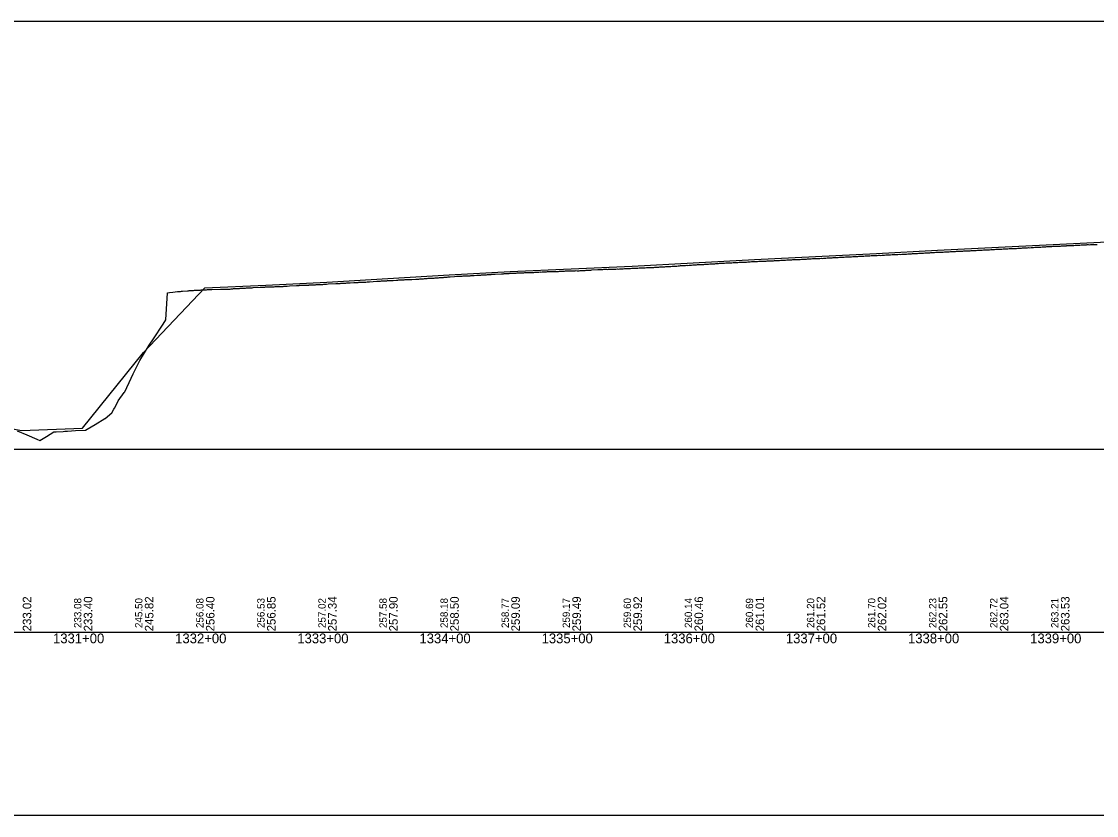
# Model space of a CAD drawing. Extents: x 2898 to 49495, y -15038 to -13538.
# Drawn here: x 22503 to 23383, y -15038 to -14388 of the extents above; entities that cross this region are included whole.
import ezdxf

# ---------------------------------------------------------------- set-up
doc = ezdxf.new("R2010")
doc.units = 0
for name, color, linetype in [('RD_DDB_Profile_EX', 7, 'Continuous'), ('RD_DDB_Profile_PR', 7, 'Continuous'), ('RD_DDB_StaTX', 7, 'Continuous'), ('RD_DDB_StripGrade', 7, 'Continuous'), ('RD_GPK_Profile_Cell', 7, 'Continuous'), ('RD_SHT_ShtClip', 7, 'Continuous')]:
    doc.layers.add(name, color=color, linetype=linetype)

msp = doc.modelspace()

# ---------------------------------------------------------------- linework, layer by layer
at = {"layer": 'RD_DDB_Profile_EX'}
for points in [[(23256.97, -14577.17), (23257.97, -14577.18), (23258.97, -14577.07), (23259.97, -14577.04), (23260.97, -14576.99), (23261.96, -14577.01), (23262.97, -14576.98), (23263.97, -14576.82), (23264.96, -14576.73), (23265.97, -14576.71), (23266.96, -14576.8), (23267.96, -14576.66), (23268.96, -14576.57), (23269.96, -14576.52), (23270.97, -14576.51), (23271.96, -14576.5), (23272.97, -14576.4), (23273.96, -14576.41), (23274.97, -14576.33), (23275.97, -14576.28), (23276.97, -14576.2), (23277.97, -14576.15), (23278.96, -14576.15), (23279.96, -14576.07), (23280.97, -14576.05), (23281.96, -14576.05), (23282.96, -14575.96), (23283.96, -14575.92), (23284.96, -14575.82), (23285.97, -14575.78), (23286.96, -14575.76), (23287.96, -14575.63), (23288.97, -14575.63), (23289.96, -14575.6), (23290.97, -14575.5), (23291.96, -14575.49), (23292.96, -14575.44), (23293.97, -14575.37), (23294.96, -14575.36), (23295.96, -14575.29), (23296.97, -14575.15), (23297.96, -14575.13), (23298.96, -14575.08), (23299.96, -14574.99), (23300.96, -14574.94), (23301.96, -14574.86), (23302.96, -14574.89), (23303.96, -14574.8), (23304.97, -14574.71), (23305.96, -14574.73), (23306.96, -14574.67), (23307.96, -14574.59), (23308.96, -14574.6), (23309.96, -14574.54), (23310.96, -14574.44), (23311.96, -14574.4), (23312.96, -14574.36), (23313.96, -14574.35), (23314.96, -14574.33), (23315.96, -14574.24), (23316.96, -14574.2), (23317.96, -14574.16), (23318.96, -14574.12), (23319.96, -14574.06), (23320.96, -14574.01), (23321.96, -14573.93), (23322.96, -14573.87), (23323.96, -14573.82), (23324.96, -14573.78), (23325.96, -14573.73), (23326.96, -14573.7), (23327.96, -14573.59), (23328.95, -14573.63), (23329.96, -14573.54), (23330.96, -14573.48), (23331.96, -14573.44), (23332.96, -14573.34), (23333.96, -14573.29), (23334.96, -14573.19), (23335.96, -14573.13), (23336.96, -14573.13), (23337.96, -14573.08), (23338.96, -14573.04), (23339.96, -14572.99), (23340.96, -14572.93), (23341.96, -14572.83), (23342.96, -14572.77), (23343.96, -14572.75), (23344.96, -14572.78), (23345.96, -14572.66), (23346.96, -14572.59), (23347.96, -14572.52), (23348.96, -14572.46), (23349.96, -14572.46), (23350.96, -14572.41), (23351.38, -14572.39), (23351.95, -14572.37), (23352.95, -14572.43), (23353.96, -14572.41), (23354.96, -14572.22), (23355.96, -14572.12)], [(23355.96, -14572.12), (23356.96, -14572.12), (23357.96, -14572.02), (23358.96, -14571.98), (23359.34, -14571.96), (23359.96, -14571.96), (23360.96, -14571.92), (23361.96, -14571.87), (23362.96, -14571.8), (23363.96, -14571.8), (23364.96, -14571.75), (23365.96, -14571.63), (23366.96, -14571.61), (23367.3, -14571.61), (23367.96, -14571.6), (23368.96, -14571.51), (23369.96, -14571.46), (23370.96, -14571.4), (23371.96, -14571.36), (23372.96, -14571.31), (23373.96, -14571.27), (23375.26, -14571.19), (23375.96, -14571.12), (23376.96, -14571.08), (23377.96, -14571.16), (23378.96, -14571.12), (23379.96, -14571.11), (23380.96, -14571.02), (23381.96, -14571.01), (23383.21, -14570.94), (23383.96, -14570.95)], [(23061.95, -14587.34), (23062.95, -14587.13), (23063.95, -14587.09), (23064.96, -14587.05), (23065.96, -14586.99), (23066.95, -14586.85), (23067.95, -14586.81), (23068.96, -14586.79), (23069.96, -14586.83), (23070.95, -14586.77), (23071.95, -14586.67), (23072.95, -14586.54), (23073.95, -14586.49), (23074.95, -14586.43), (23075.96, -14586.39), (23076.96, -14586.34), (23077.95, -14586.24), (23078.95, -14586.23), (23079.95, -14586.15), (23080.95, -14586.06), (23081.95, -14586.1), (23082.95, -14586.01), (23083.95, -14586.06), (23084.95, -14586.01), (23085.95, -14585.86), (23086.95, -14585.83), (23087.95, -14585.75), (23088.95, -14585.72), (23089.95, -14585.7), (23090.95, -14585.61), (23091.95, -14585.56), (23092.95, -14585.46), (23093.95, -14585.41), (23094.95, -14585.42), (23095.95, -14585.42), (23096.94, -14585.37), (23097.94, -14585.27), (23098.95, -14585.18), (23099.94, -14585.12), (23100.95, -14585.06), (23101.94, -14585.01), (23102.94, -14585.01), (23103.94, -14585.02), (23104.94, -14584.97), (23105.94, -14584.86), (23106.93, -14584.76), (23107.94, -14584.76), (23108.94, -14584.71), (23109.94, -14584.7), (23110.94, -14584.74), (23111.93, -14584.73), (23112.93, -14584.59), (23113.94, -14584.5), (23114.93, -14584.49), (23115.94, -14584.49), (23116.94, -14584.48), (23117.94, -14584.27), (23118.94, -14584.26), (23119.94, -14584.2), (23120.94, -14584.18), (23121.94, -14584.12), (23122.94, -14584.02), (23123.94, -14584.01), (23124.94, -14583.95), (23125.94, -14583.9), (23126.94, -14583.81), (23127.94, -14583.75), (23128.95, -14583.72), (23129.94, -14583.67), (23130.94, -14583.62), (23131.95, -14583.6), (23132.94, -14583.54), (23133.95, -14583.48), (23134.95, -14583.43), (23135.95, -14583.33), (23136.95, -14583.32), (23137.95, -14583.21), (23138.95, -14583.32), (23139.95, -14583.24), (23140.95, -14583.17), (23141.95, -14583.16), (23142.95, -14582.97), (23143.95, -14582.99), (23144.95, -14582.95), (23145.95, -14582.9), (23146.95, -14582.85), (23147.96, -14582.8), (23148.95, -14582.65), (23149.95, -14582.64), (23150.95, -14582.58), (23151.95, -14582.58), (23152.44, -14582.53), (23152.96, -14582.51), (23153.95, -14582.45), (23154.95, -14582.43), (23155.96, -14582.42), (23156.96, -14582.36), (23157.96, -14582.31), (23158.95, -14582.35), (23159.96, -14582.24), (23160.4, -14582.22)], [(23160.4, -14582.22), (23160.95, -14582.19), (23161.95, -14582.15), (23162.96, -14581.98), (23163.96, -14581.96), (23164.95, -14581.97), (23165.96, -14581.96), (23166.96, -14581.82), (23167.96, -14581.8), (23168.36, -14581.78), (23168.96, -14581.77), (23169.96, -14581.72), (23170.96, -14581.58), (23171.96, -14581.59), (23172.96, -14581.5), (23173.96, -14581.5), (23174.96, -14581.46), (23175.96, -14581.32), (23176.31, -14581.32), (23176.96, -14581.31), (23177.96, -14581.2), (23178.96, -14581.15), (23179.96, -14581.16), (23180.97, -14581.2), (23181.97, -14581.04), (23182.96, -14580.99), (23183.96, -14580.87), (23184.27, -14580.87), (23184.96, -14580.86), (23185.96, -14580.82), (23186.96, -14580.74), (23187.97, -14580.72), (23188.96, -14580.66), (23189.96, -14580.58), (23190.96, -14580.55), (23192.23, -14580.55), (23192.96, -14580.49), (23193.97, -14580.42), (23194.96, -14580.34), (23195.96, -14580.29), (23196.96, -14580.24), (23197.96, -14580.19), (23198.96, -14580.16), (23200.19, -14580.1), (23200.97, -14580.09), (23201.97, -14580.03), (23202.97, -14580.03), (23203.97, -14579.91), (23204.97, -14579.85), (23205.96, -14579.83), (23206.96, -14579.91), (23208.15, -14579.75), (23208.96, -14579.72), (23209.96, -14579.62), (23210.96, -14579.56), (23211.96, -14579.51), (23212.96, -14579.47), (23213.97, -14579.47), (23214.97, -14579.43), (23216.1, -14579.34), (23216.97, -14579.28), (23217.96, -14579.25), (23218.97, -14579.23), (23219.97, -14579.13), (23220.97, -14579.09), (23221.97, -14579.04), (23222.96, -14579.11), (23224.06, -14579.04), (23224.96, -14578.93), (23225.96, -14578.89), (23226.96, -14578.93), (23227.97, -14578.92), (23228.96, -14578.72), (23229.97, -14578.69), (23230.96, -14578.63), (23232.02, -14578.58), (23232.96, -14578.49), (23233.96, -14578.43), (23234.96, -14578.38), (23235.96, -14578.35), (23236.96, -14578.26), (23237.96, -14578.23), (23238.96, -14578.21), (23239.98, -14578.2), (23240.96, -14578.08), (23241.96, -14578.02), (23242.96, -14577.92), (23243.96, -14577.88), (23244.96, -14577.86), (23245.96, -14577.78), (23246.96, -14577.71), (23247.96, -14577.7), (23248.96, -14577.67), (23249.97, -14577.58), (23250.96, -14577.52), (23251.97, -14577.39), (23252.96, -14577.35), (23253.97, -14577.3), (23254.96, -14577.24), (23255.97, -14577.18), (23256.97, -14577.17)], [(22871.38, -14596.48), (22872.17, -14596.44), (22872.96, -14596.44), (22873.92, -14596.39), (22876.12, -14596.26), (22876.92, -14596.18), (22877.72, -14596.14), (22878.51, -14596.1), (22879.31, -14596.06), (22880.11, -14595.98), (22880.9, -14595.9), (22881.88, -14595.85), (22882.49, -14595.82), (22883.28, -14595.74), (22884.07, -14595.74), (22884.87, -14595.7), (22885.66, -14595.58), (22886.45, -14595.54), (22887.25, -14595.66), (22888.03, -14595.66), (22888.83, -14595.38), (22889.84, -14595.33), (22890.43, -14595.3), (22891.22, -14595.26), (22896.25, -14594.95), (22897.05, -14595.03), (22897.86, -14594.99), (22898.66, -14594.83), (22899.46, -14594.87), (22900.26, -14594.79), (22901.07, -14594.75), (22901.87, -14594.79), (22902.67, -14594.67), (22903.48, -14594.59), (22904.28, -14594.51), (22905.09, -14594.51), (22905.89, -14594.51), (22906.7, -14594.51), (22907.51, -14594.47), (22908.32, -14594.39), (22909.13, -14594.35), (22909.93, -14594.35), (22910.73, -14594.27), (22913.13, -14594.19), (22913.95, -14594.19), (22914.76, -14594.15), (22915.56, -14594.03), (22916.37, -14593.99), (22917.18, -14593.99), (22917.98, -14593.99), (22918.79, -14593.99), (22919.6, -14593.91), (22920.4, -14593.82), (22921.2, -14593.86), (22921.67, -14593.86), (22922.01, -14593.87), (22922.82, -14593.82), (22923.61, -14593.7), (22924.42, -14593.7), (22925.23, -14593.66), (22926.04, -14593.66), (22926.83, -14593.54), (22927.64, -14593.5), (22928.46, -14593.54), (22929.63, -14593.5), (22933.26, -14593.38), (22934.08, -14593.22), (22934.89, -14593.26), (22935.69, -14593.26), (22936.5, -14593.18), (22937.58, -14593.18), (22938.12, -14593.18), (22938.93, -14593.02), (22939.74, -14593.02), (22940.55, -14593.06), (22941.36, -14593.02), (22942.17, -14593.02), (22942.98, -14593.02), (22943.79, -14592.94), (22944.6, -14592.9), (22945.54, -14592.84), (22946.23, -14592.74), (22947.05, -14592.82), (22947.87, -14592.82), (22948.67, -14592.66), (22949.48, -14592.66), (22950.3, -14592.57), (22953.5, -14592.61), (22954.23, -14592.54), (22955.04, -14592.5), (22955.85, -14592.58), (22956.66, -14592.58), (22957.46, -14592.42), (22958.27, -14592.54), (22959.08, -14592.58), (22959.89, -14592.54), (22960.7, -14592.3), (22961.51, -14592.26), (22962.31, -14592.22), (22963.13, -14592.18), (22963.93, -14592.18)], [(22963.93, -14592.18), (22964.75, -14592.18), (22965.55, -14592.14), (22966.37, -14592.09), (22967.18, -14592.05), (22967.98, -14592.01), (22968.81, -14591.97), (22969.61, -14591.93), (22970.43, -14591.89), (22975.19, -14591.51), (22976, -14591.51), (22976.8, -14591.51), (22977.61, -14591.47), (22978.42, -14591.43), (22979.22, -14591.39), (22980.03, -14591.35), (22980.84, -14591.35), (22981.65, -14591.35), (22982.46, -14591.35), (22983.27, -14591.39), (22984.07, -14591.35), (22984.98, -14591.22), (22985.33, -14591.24), (22985.96, -14591.23), (22986.96, -14591.18), (22987.95, -14591.23), (22988.96, -14591.1), (22989.96, -14591.08), (22990.96, -14590.99), (22991.96, -14591.08), (22992.96, -14591.02), (22993.29, -14590.97), (22993.96, -14590.88), (22994.96, -14590.96), (22995.96, -14590.86), (22996.95, -14590.69), (22997.96, -14590.69), (22998.96, -14590.6), (22999.96, -14590.6), (23001.25, -14590.6), (23001.96, -14590.59), (23002.96, -14590.52), (23003.95, -14590.44), (23004.96, -14590.49), (23005.95, -14590.45), (23006.96, -14590.29), (23007.96, -14590.29), (23009.2, -14590.23), (23009.96, -14590.22), (23010.96, -14590.13), (23011.96, -14590.2), (23012.95, -14590.24), (23013.96, -14590.08), (23014.96, -14589.98), (23015.96, -14589.95), (23017.16, -14589.89), (23017.96, -14589.84), (23018.96, -14589.78), (23019.96, -14589.72), (23020.96, -14589.72), (23021.95, -14589.67), (23022.95, -14589.61), (23023.96, -14589.55), (23025.12, -14589.47), (23025.96, -14589.4), (23026.96, -14589.32), (23027.96, -14589.35), (23028.96, -14589.34), (23029.96, -14589.17), (23030.96, -14589.07), (23031.95, -14589.01), (23033.08, -14589.01), (23033.95, -14589), (23034.95, -14588.91), (23035.96, -14588.87), (23036.95, -14588.74), (23037.96, -14588.68), (23038.95, -14588.68), (23039.95, -14588.63), (23041.03, -14588.55), (23041.96, -14588.46), (23042.96, -14588.32), (23043.96, -14588.31), (23044.95, -14588.25), (23045.95, -14588.24), (23046.96, -14588.1), (23047.96, -14588.06), (23048.99, -14588.1), (23049.95, -14588.01), (23050.96, -14587.93), (23051.96, -14587.89), (23052.95, -14587.76), (23053.96, -14587.72), (23054.95, -14587.71), (23055.96, -14587.64), (23056.95, -14587.52), (23057.96, -14587.52), (23058.96, -14587.44), (23059.96, -14587.37), (23060.95, -14587.36), (23061.95, -14587.34)], [(22780.31, -14601.88), (22781.03, -14601.88), (22781.76, -14601.88), (22782.49, -14601.88), (22783.21, -14601.91), (22783.93, -14601.84), (22784.65, -14601.77), (22785.38, -14601.73), (22786.39, -14601.57), (22786.84, -14601.55), (22787.57, -14601.51), (22788.3, -14601.48), (22794.35, -14601.15), (22795.06, -14601.11), (22795.8, -14601.08), (22796.53, -14601.04), (22797.25, -14600.93), (22797.98, -14600.85), (22798.72, -14600.85), (22799.45, -14600.78), (22800.18, -14600.74), (22800.93, -14600.74), (22801.66, -14600.71), (22802.39, -14600.63), (22803.13, -14600.6), (22803.87, -14600.48), (22804.62, -14600.48), (22805.36, -14600.41), (22806.1, -14600.37), (22806.85, -14600.41), (22807.59, -14600.37), (22810.26, -14600.23), (22810.72, -14600.2), (22811.47, -14600.09), (22812.21, -14600.05), (22812.96, -14600.01), (22813.72, -14599.98), (22814.47, -14599.94), (22815.22, -14599.9), (22815.98, -14599.82), (22816.73, -14599.82), (22817.49, -14599.79), (22818.25, -14599.75), (22819.01, -14599.71), (22819.77, -14599.71), (22820.53, -14599.67), (22821.3, -14599.63), (22822.06, -14599.59), (22822.84, -14599.59), (22826.18, -14599.41), (22828.71, -14599.27), (22829.47, -14599.15), (22830.24, -14599.12), (22830.99, -14599.04), (22831.75, -14599.08), (22832.53, -14599.08), (22833.29, -14598.92), (22834.14, -14598.91), (22834.84, -14598.84), (22835.61, -14598.76), (22836.39, -14598.69), (22837.17, -14598.61), (22837.95, -14598.53), (22838.73, -14598.49), (22839.52, -14598.49), (22840.31, -14598.52), (22841.1, -14598.48), (22842.09, -14598.39), (22842.43, -14598.36), (22843.21, -14598.32), (22844.01, -14598.28), (22844.79, -14598.24), (22845.58, -14598.12), (22846.37, -14598.12), (22847.16, -14598), (22847.95, -14597.92), (22848.74, -14597.92), (22849.53, -14597.89), (22850.32, -14597.85), (22851.11, -14597.77), (22851.91, -14597.73), (22852.69, -14597.61), (22853.5, -14597.57), (22854.28, -14597.57), (22858.01, -14597.22), (22859.54, -14597.07), (22860.32, -14597.03), (22861.11, -14596.99), (22861.9, -14596.92), (22862.69, -14596.88), (22863.47, -14596.96), (22864.26, -14596.92), (22865.05, -14596.76), (22865.97, -14596.79), (22866.63, -14596.76), (22867.42, -14596.76), (22868.2, -14596.68), (22869, -14596.64), (22869.79, -14596.56), (22870.59, -14596.56), (22871.38, -14596.48)], [(22515.83, -14730.49), (22518.36, -14731.61), (22521.16, -14729.88), (22523.79, -14728.25), (22529.92, -14724.44), (22531.74, -14724.33), (22537.38, -14724.01), (22538.77, -14723.95), (22539.96, -14723.87), (22541, -14723.8), (22547.66, -14723.39), (22555.67, -14722.9), (22557.15, -14722.2), (22563.57, -14718.35), (22571.53, -14713.58), (22571.96, -14713.33), (22577.34, -14708.74), (22579.05, -14705.73), (22579.49, -14704.93), (22580.76, -14702.6), (22582.46, -14699.05), (22587.45, -14692.22), (22587.85, -14691.67), (22593.25, -14680.57), (22594.93, -14676.8), (22595.41, -14675.85), (22600.34, -14665.99), (22603.36, -14661), (22607.99, -14653.36), (22611.32, -14648.31), (22619.28, -14636.24), (22621.67, -14632.6), (22622.91, -14610.69), (22624.49, -14610.45), (22627.24, -14610.07), (22631.09, -14609.53), (22631.66, -14609.47), (22632.33, -14609.43), (22632.98, -14609.37), (22633.65, -14609.37), (22634.32, -14609.33), (22635.19, -14609.28), (22639.31, -14609.05), (22640.01, -14608.91), (22640.71, -14608.77), (22641.41, -14608.77), (22642.12, -14608.77), (22642.82, -14608.74), (22643.15, -14608.69), (22643.53, -14608.63), (22644.23, -14608.56), (22644.95, -14608.52), (22645.66, -14608.52), (22646.37, -14608.45), (22647.09, -14608.34), (22648.44, -14608.31), (22649.16, -14608.34), (22649.87, -14608.34), (22650.58, -14608.2), (22651.3, -14608.13), (22652.02, -14608.09), (22652.74, -14608.09), (22653.46, -14608.09), (22654.19, -14608.05), (22654.92, -14608.01), (22655.64, -14607.94), (22656.38, -14607.98), (22657.1, -14607.94), (22657.82, -14607.83), (22658.53, -14607.83), (22659.25, -14607.8), (22666.23, -14607.6), (22667.02, -14607.56), (22667.69, -14607.53), (22668.41, -14607.56), (22669.13, -14607.67), (22669.85, -14607.71), (22670.57, -14607.71), (22671.29, -14607.71), (22672.01, -14607.67), (22672.73, -14607.64), (22673.44, -14607.57), (22674.16, -14607.46), (22674.98, -14607.34), (22675.58, -14607.28), (22676.29, -14607.25), (22677.01, -14607.14), (22677.72, -14607.1), (22678.43, -14607.07), (22681.06, -14606.93), (22681.77, -14606.93), (22682.48, -14606.89), (22683.19, -14606.79), (22683.9, -14606.82), (22684.62, -14606.79), (22685.32, -14606.68), (22686.03, -14606.72), (22686.74, -14606.72), (22687.45, -14606.61), (22688.15, -14606.58), (22688.86, -14606.54)], [(22688.86, -14606.54), (22689.56, -14606.54), (22690.26, -14606.51), (22690.95, -14606.44), (22691.66, -14606.47), (22692.35, -14606.41), (22693.05, -14606.34), (22698.85, -14606.03), (22700.39, -14605.94), (22701.11, -14605.91), (22701.83, -14605.87), (22702.54, -14605.87), (22703.25, -14605.8), (22703.96, -14605.8), (22704.67, -14605.77), (22705.37, -14605.77), (22706.08, -14605.77), (22706.81, -14605.7), (22707.49, -14605.66), (22708.2, -14605.66), (22708.9, -14605.59), (22709.61, -14605.56), (22710.31, -14605.56), (22711.19, -14605.51), (22711.89, -14605.48), (22712.59, -14605.48), (22713.29, -14605.44), (22713.98, -14605.41), (22714.77, -14605.33), (22715.38, -14605.27), (22716.08, -14605.27), (22716.77, -14605.27), (22717.48, -14605.27), (22718.16, -14605.23), (22718.87, -14605.13), (22719.55, -14605.13), (22720.26, -14605.09), (22720.95, -14605.02), (22722.73, -14604.93), (22728.62, -14604.6), (22729.3, -14604.6), (22730, -14604.53), (22730.69, -14604.53), (22731.38, -14604.43), (22732.07, -14604.36), (22732.76, -14604.33), (22733.44, -14604.33), (22734.13, -14604.29), (22734.82, -14604.29), (22735.51, -14604.29), (22736.2, -14604.29), (22736.89, -14604.26), (22737.57, -14604.26), (22738.26, -14604.22), (22738.64, -14604.19), (22738.95, -14604.16), (22739.64, -14604.16), (22741.93, -14604.04), (22742.62, -14604.04), (22743.3, -14604.01), (22743.99, -14603.97), (22744.67, -14603.9), (22745.36, -14603.9), (22746.04, -14603.83), (22746.73, -14603.8), (22747.41, -14603.76), (22748.11, -14603.73), (22748.79, -14603.66), (22749.48, -14603.66), (22750.18, -14603.66), (22750.87, -14603.59), (22751.57, -14603.56), (22752.27, -14603.45), (22752.99, -14603.38), (22754.56, -14603.3), (22760.76, -14602.99), (22761.44, -14602.95), (22762.12, -14602.95), (22762.78, -14602.95), (22763.47, -14602.88), (22764.15, -14602.85), (22764.84, -14602.78), (22765.52, -14602.75), (22766.21, -14602.71), (22766.9, -14602.68), (22767.59, -14602.64), (22768.28, -14602.57), (22768.98, -14602.54), (22769.68, -14602.5), (22770.47, -14602.47), (22771.08, -14602.53), (22771.79, -14602.46), (22772.5, -14602.36), (22775.34, -14602.2), (22776.04, -14602.17), (22776.75, -14602.13), (22777.45, -14602.1), (22778.43, -14602.07), (22778.88, -14602.03), (22779.59, -14601.95), (22780.31, -14601.88)], [(22499.91, -14723.43), (22507.87, -14726.96), (22515.83, -14730.49)]]:
    msp.add_lwpolyline(points, dxfattribs=at)
at = {"layer": 'RD_DDB_Profile_PR'}
for points in [[(23053.38, -14586.14), (23103.38, -14583.42), (23153.38, -14580.88), (23203.38, -14578.38), (23253.38, -14575.73), (23303.38, -14573.25), (23353.38, -14570.82), (23403.38, -14568.35)], [(22453.38, -14713.86), (22503.38, -14723.37), (22553.38, -14721.44), (22603.38, -14659.37), (22653.38, -14606.49), (22703.38, -14604.2), (22753.38, -14601.76), (22803.38, -14598.96), (22853.38, -14595.97), (22903.38, -14593), (22953.38, -14591.01), (23003.38, -14588.88), (23053.38, -14586.14)]]:
    msp.add_lwpolyline(points, dxfattribs=at)
at = {"layer": 'RD_GPK_Profile_Cell'}
msp.add_line((2976.05, -14888.47), (48721.13, -14888.47), dxfattribs=at)
at = {"layer": 'RD_SHT_ShtClip'}
for points in [[(22475.38, -14388.47), (22475.38, -14888.47), (23975.38, -14888.47), (23975.38, -14888.47), (23975.38, -14388.47), (23975.38, -14388.47)], [(22455.38, -14738.47), (23995.38, -14738.47), (23995.38, -15038.47), (22455.38, -15038.47)]]:
    msp.add_lwpolyline(points, close=True, dxfattribs=at)

# ---------------------------------------------------------------- texts
at = {"layer": 'RD_DDB_StaTX'}
for s, p in [('1331+00', (22529.18, -14897.47)), ('1332+00', (22629.18, -14897.47)), ('1333+00', (22729.18, -14897.47)), ('1334+00', (22829.18, -14897.47)), ('1335+00', (22929.18, -14897.47)), ('1336+00', (23029.18, -14897.47)), ('1337+00', (23129.18, -14897.47)), ('1338+00', (23229.18, -14897.47)), ('1339+00', (23329.18, -14897.47))]:
    msp.add_text(s, height=8, dxfattribs=at).set_placement(p)
at = {"layer": 'RD_DDB_StripGrade'}
for s, height, p in [('233.02', 7, (22511.38, -14887.72)), ('233.08', 6, (22552.38, -14884.98)), ('233.40', 7, (22561.38, -14887.72)), ('245.50', 6, (22602.38, -14884.98)), ('245.82', 7, (22611.38, -14887.72)), ('256.08', 6, (22652.38, -14884.98)), ('256.40', 7, (22661.38, -14887.72)), ('256.53', 6, (22702.38, -14884.98)), ('256.85', 7, (22711.38, -14887.72)), ('257.02', 6, (22752.38, -14884.98)), ('257.34', 7, (22761.38, -14887.72)), ('257.58', 6, (22802.38, -14884.98)), ('257.90', 7, (22811.38, -14887.72)), ('258.18', 6, (22852.38, -14884.98)), ('258.50', 7, (22861.38, -14887.72)), ('258.77', 6, (22902.38, -14884.98)), ('259.09', 7, (22911.38, -14887.72)), ('259.17', 6, (22952.38, -14884.98)), ('259.49', 7, (22961.38, -14887.72)), ('259.60', 6, (23002.38, -14884.98)), ('259.92', 7, (23011.38, -14887.72)), ('260.14', 6, (23052.38, -14884.98)), ('260.46', 7, (23061.38, -14887.72)), ('260.69', 6, (23102.38, -14884.98)), ('261.01', 7, (23111.38, -14887.72)), ('261.20', 6, (23152.38, -14884.98)), ('261.52', 7, (23161.38, -14887.72)), ('261.70', 6, (23202.38, -14884.98)), ('262.02', 7, (23211.38, -14887.72)), ('262.23', 6, (23252.38, -14884.98)), ('262.55', 7, (23261.38, -14887.72)), ('262.72', 6, (23302.38, -14884.98)), ('263.04', 7, (23311.38, -14887.72)), ('263.21', 6, (23352.38, -14884.98)), ('263.53', 7, (23361.38, -14887.72))]:
    msp.add_text(s, height=height, rotation=90, dxfattribs=at).set_placement(p)

doc.saveas('drawing.dxf')
